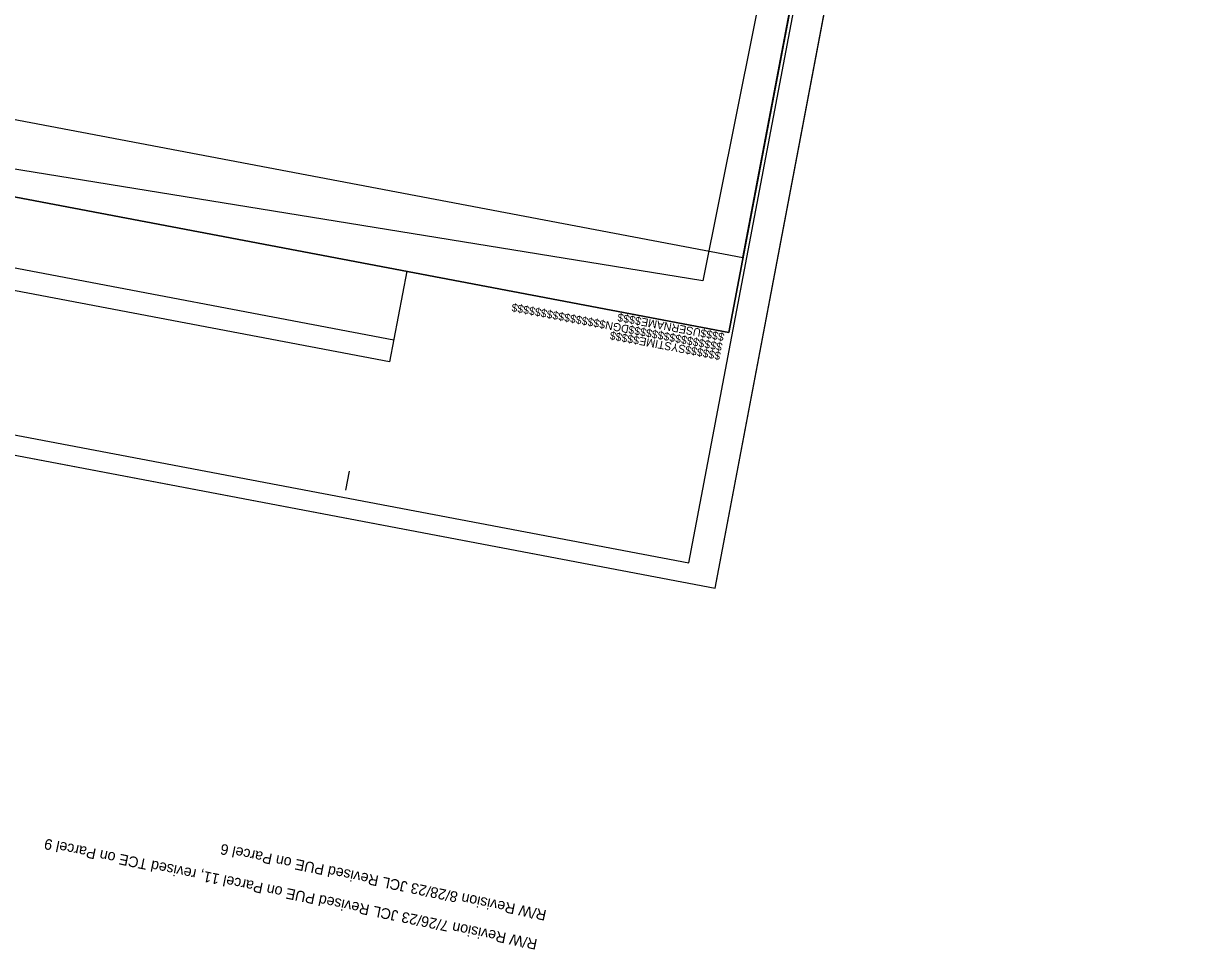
# Model space of a CAD drawing. Extents: x 1615685 to 1617075, y 899072 to 901363.
# Drawn here: x 1616307 to 1617075, y 899072 to 899679 of the extents above; entities that cross this region are included whole.
import ezdxf

# ---------------------------------------------------------------- set-up
doc = ezdxf.new("R2010")
doc.units = 0
for name, color, linetype in [('Exist Plan Preparation Drainage Flow Arrows', 7, 'Continuous'), ('Exist Plan Preparation Drainage Notes Label', 7, 'Continuous'), ('Exist Structure Minor Pipes CMP 24 Inch Text', 7, 'Continuous'), ('Exist Structure Minor Pipes RCP 12 Inch SizeText', 7, 'Continuous'), ('Prop Drainage Structure Catch Basin Grate 840 03E CELL', 7, 'Continuous'), ('Prop Drainage Structure Drop Inlet Grate 840 16 CELL', 7, 'Continuous'), ('Prop Drainage Structure Plot Symbol 20 Scale', 7, 'Continuous'), ('Scratch_Level_3', 7, 'Continuous'), ('Scratch_Level_8', 7, 'Continuous')]:
    doc.layers.add(name, color=color, linetype=linetype)

msp = doc.modelspace()

# ---------------------------------------------------------------- linework, layer by layer
at = {"layer": 'Exist Plan Preparation Drainage Flow Arrows'}
msp.add_lwpolyline([(1616744, 899325.3), (1617054.75, 900962.05), (1616018.28, 901158.86), (1615707.51, 899522.1)], close=True, dxfattribs=at)
at = {"layer": 'Exist Plan Preparation Drainage Notes Label'}
msp.add_lwpolyline([(1616761.22, 899308.8), (1617075.25, 900962.75), (1615999.47, 901167.01), (1615685.44, 899513.06)], close=True, dxfattribs=at)
at = {"layer": 'Exist Structure Minor Pipes CMP 24 Inch Text'}
for p, q in [((1616761.22, 899308.8), (1617075.25, 900962.75)), ((1615685.44, 899513.06), (1616761.22, 899308.8))]:
    msp.add_line(p, q, dxfattribs=at)
at = {"layer": 'Prop Drainage Structure Catch Basin Grate 840 03E CELL'}
msp.add_lwpolyline([(1616779.49, 899525.69), (1617040.64, 900901.13), (1616216.84, 901057.54), (1616181.54, 900871.6), (1615973.76, 900911.05), (1615747.91, 899721.55)], close=True, dxfattribs=at)
at = {"layer": 'Prop Drainage Structure Drop Inlet Grate 840 16 CELL'}
msp.add_lwpolyline([(1615738.61, 899672.4), (1616770.16, 899476.57), (1617049.96, 900950.24), (1616226.17, 901106.65), (1616181.54, 900871.6), (1615973.76, 900911.05)], close=True, dxfattribs=at)
at = {"layer": 'Prop Drainage Structure Plot Symbol 20 Scale'}
msp.add_lwpolyline([(1616187.49, 901058.27), (1617032.97, 900874.07), (1617012.18, 900781.12), (1616950.6, 900773.34), (1616752.73, 900760.58), (1616722.43, 900593.62), (1616951.14, 900496.73), (1616753.23, 899510.43), (1615915.8, 899646.19), (1615751.76, 899738.03), (1615999.36, 900929.08), (1616157.93, 900902)], close=True, dxfattribs=at)
at = {"layer": 'Scratch_Level_3'}
msp.add_line((1616550.36, 899471.5), (1615773.59, 899618.97), dxfattribs=at)
msp.add_lwpolyline([(1616547.67, 899457.2), (1615770.89, 899604.69), (1615782.16, 899664.17), (1616558.93, 899516.68)], close=True, dxfattribs=at)
at = {"layer": 'Scratch_Level_8'}
for p, q in [((1616770.16, 899476.57), (1616770.16, 899476.57)), ((1616518.97, 899373.13), (1616521.31, 899385.41))]:
    msp.add_line(p, q, dxfattribs=at)
for points in [[(1616018.4, 901146.14), (1615738.59, 899672.43), (1616770.16, 899476.57), (1617049.96, 900950.25)], [(1616770.16, 899476.57), (1615738.61, 899672.4), (1615981.06, 900949.58), (1616128.49, 900921.6), (1616165.82, 901118.12), (1617049.96, 900950.25)]]:
    msp.add_lwpolyline(points, close=True, dxfattribs=at)

# ---------------------------------------------------------------- texts
at = {"layer": 'Exist Structure Minor Pipes RCP 12 Inch SizeText'}
for s, p in [('R/W Revision 7/26/23 JCL Revised PUE on Parcel 11, revised TCE on Parcel 9', (1616644.99, 899078.23)), ('R/W Revision 8/28/23 JCL Revised PUE on Parcel 6', (1616650.99, 899097.31))]:
    msp.add_text(s, height=7, rotation=168.41352, dxfattribs=at).set_placement(p)
at = {"layer": 'Scratch_Level_8'}
for s, p in [('$$$$$$$$$$$$$$$$DGN$$$$$$$$$$$$$$$$', (1616766.41, 899469.5)), ('$$$$USERNAME$$$$', (1616767.62, 899475.94)), ('$$$$$$SYSTIME$$$$$', (1616765.3, 899463.53))]:
    msp.add_text(s, height=5.25, rotation=169.24937, dxfattribs=at).set_placement(p)

doc.saveas('drawing.dxf')
